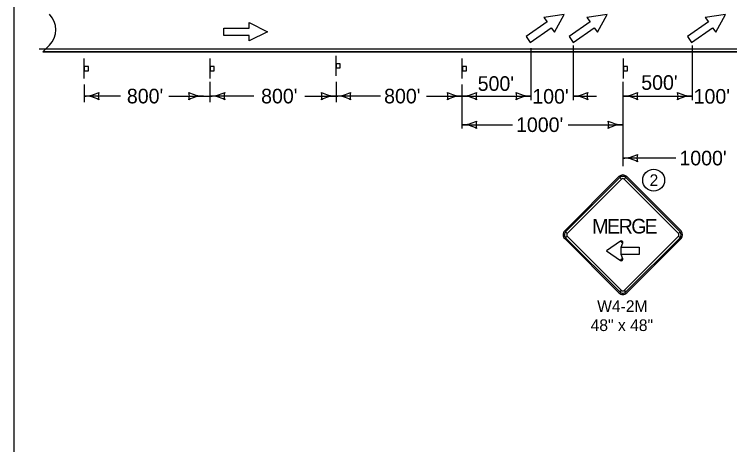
# Model space of a CAD drawing. Extents: x 10133 to 2270741, y 5363 to 1733450.
# Drawn here: x 28133 to 29111, y 8710 to 9298 of the extents above; entities that cross this region are included whole.
import ezdxf

# ---------------------------------------------------------------- set-up
doc = ezdxf.new("R2010")
doc.units = 0
for name, color, linetype in [('dsnNonPlotable', 7, 'Continuous'), ('dsnShtPlotShapeBatchPrint', 7, 'Continuous'), ('dsnStdBorder', 7, 'Continuous'), ('Level 12', 7, 'Continuous'), ('Level 2', 7, 'Continuous'), ('SheetBorder', 7, 'Continuous'), ('SheetText', 7, 'Continuous')]:
    doc.layers.add(name, color=color, linetype=linetype)

msp = doc.modelspace()

# ---------------------------------------------------------------- linework, layer by layer
at = {"layer": 'dsnNonPlotable'}
for p, q in [((28884.31, 9298.24), (28856.66, 9294.14)), ((28856.66, 9294.14), (28860.96, 9288)), ((28871, 9273.67), (28884.31, 9298.24)), ((28943.08, 9298.24), (28915.43, 9294.14)), ((28915.43, 9294.14), (28919.73, 9288)), ((28929.77, 9273.67), (28943.08, 9298.24)), ((29104.88, 9298.24), (29077.24, 9294.14)), ((29077.24, 9294.14), (29081.54, 9288)), ((29091.58, 9273.67), (29104.88, 9298.24)), ((28860.96, 9288), (28832.3, 9267.93)), ((28919.73, 9288), (28891.07, 9267.93)), ((29081.54, 9288), (29052.87, 9267.93)), ((28838.03, 9259.74), (28866.7, 9279.81)), ((28866.7, 9279.81), (28871, 9273.67)), ((28896.8, 9259.74), (28925.47, 9279.81)), ((28925.47, 9279.81), (28929.77, 9273.67)), ((29058.61, 9259.74), (29087.28, 9279.81)), ((29087.28, 9279.81), (29091.58, 9273.67)), ((28832.3, 9267.93), (28838.03, 9259.74)), ((28891.07, 9267.93), (28896.8, 9259.74)), ((29052.87, 9267.93), (29058.61, 9259.74)), ((28180.53, 9255.86), (28171.75, 9247.08)), ((28166.53, 9251.04), (29674.01, 9251.04))]:
    msp.add_line(p, q, dxfattribs=at)
msp.add_arc((28159.32, 9277.08), 30, 315, 45, dxfattribs=at)
at = {"layer": 'dsnShtPlotShapeBatchPrint'}
msp.add_circle((29006.75, 9071.41), 15, dxfattribs=at)
at = {"layer": 'dsnStdBorder'}
for p, q in [((28959.31, 9076.33), (28885.06, 9002.08)), ((28960.64, 9075), (28962.85, 9072.8)), ((28966.38, 9072.8), (28968.59, 9075)), ((29044.16, 9002.08), (28969.92, 9076.33)), ((28888.6, 8998.55), (28886.39, 9000.76)), ((29042.84, 9000.76), (29040.63, 8998.55)), ((28885.06, 8991.48), (28959.31, 8917.23)), ((28886.39, 8992.8), (28888.6, 8995.01)), ((28969.92, 8917.23), (29044.16, 8991.48)), ((29040.63, 8995.01), (29042.84, 8992.8)), ((28961.5, 8988.19), (28962.58, 8986.47)), ((28962.58, 8986.47), (28964.51, 8985.82)), ((28962.58, 8963.34), (28961.5, 8961.63)), ((28964.51, 8963.99), (28962.58, 8963.34)), ((28962.85, 8920.77), (28960.64, 8918.56)), ((28968.59, 8918.56), (28966.38, 8920.77))]:
    msp.add_line(p, q, dxfattribs=at)
for points in [[(28960.64, 9075), (28886.39, 9000.76), (28888.6, 8998.55), (28962.85, 9072.8), (28960.64, 9075)], [(29042.84, 9000.76), (28968.59, 9075), (28966.38, 9072.8), (29040.63, 8998.55), (29042.84, 9000.76)], [(28886.39, 8992.8), (28960.64, 8918.56), (28962.85, 8920.77), (28888.6, 8995.01), (28886.39, 8992.8)], [(28968.59, 8918.56), (29042.84, 8992.8), (29040.63, 8995.01), (28966.38, 8920.77), (28968.59, 8918.56)], [(28942.27, 8974.91), (28961.5, 8961.63), (28962.58, 8963.34), (28964.51, 8963.99), (28962.52, 8969.91), (28962.52, 8979.91), (28964.51, 8985.82), (28962.58, 8986.47), (28961.5, 8988.19), (28942.27, 8974.91)], [(28986.96, 8979.91), (28986.96, 8969.91), (28962.52, 8969.91), (28962.52, 8979.91), (28986.96, 8979.91)]]:
    msp.add_lwpolyline(points, close=True, dxfattribs=at)
for centre, radius, start, end in [((28964.61, 9071.03), 7.5, 44.99999, 134.99974), ((28964.61, 9071.03), 5.62, 44.99999, 134.99974), ((28964.61, 9071.03), 2.5, 44.99999, 134.99974), ((28890.37, 8996.78), 7.5, 134.99974, 224.99995), ((28890.37, 8996.78), 5.62, 134.99974, 224.99995), ((29038.86, 8996.78), 5.62, 315.00016, 44.9998), ((29038.86, 8996.78), 7.5, 315.00016, 44.9998), ((28890.37, 8996.78), 2.5, 134.99974, 224.99995), ((29038.86, 8996.78), 2.5, 315.00016, 44.9998), ((28962.58, 8986.47), 2.03, 341.41867, 122.31243), ((28962.58, 8963.34), 2.03, 237.68753, 18.58186), ((28964.61, 8922.54), 7.5, 224.99995, 315.00016), ((28964.61, 8922.54), 5.62, 224.99995, 315.00016), ((28964.61, 8922.54), 2.5, 224.99995, 315.00016)]:
    msp.add_arc(centre, radius, start, end, dxfattribs=at)
at = {"layer": 'Level 12'}
for p, q in [((28896.54, 9255.48), (28896.54, 9180.88)), ((29059.3, 9255.48), (29059.3, 9180.88)), ((28838.72, 9252.13), (28838.72, 9180.88)), ((28399.86, 9206.09), (28399.86, 9178.34)), ((28572.44, 9206.09), (28572.44, 9178.34)), ((28964.61, 9206.09), (28964.61, 9090.8)), ((28228.05, 9202.35), (28228.05, 9178.34)), ((28744.62, 9202.35), (28744.62, 9142.32)), ((28277.9, 9186.46), (28230.85, 9186.46)), ((28343.6, 9186.46), (28399.86, 9186.46)), ((28460.08, 9186.46), (28399.86, 9186.46)), ((28529.73, 9186.46), (28572.44, 9186.46)), ((28633.22, 9186.46), (28572.44, 9186.46)), ((28696.14, 9186.46), (28744.42, 9186.46)), ((28745.22, 9186.46), (28812.94, 9186.46)), ((28812.94, 9186.46), (28838.72, 9186.46)), ((28896.54, 9186.46), (28928.54, 9186.46)), ((28965.43, 9186.46), (29034.79, 9186.46)), ((29034.79, 9186.46), (29059.3, 9186.46)), ((28744.42, 9147.32), (28813.6, 9147.32)), ((28889.64, 9147.32), (28964.61, 9147.32)), ((29037.15, 9101.68), (28964.61, 9101.68))]:
    msp.add_line(p, q, dxfattribs=at)
for centre, radius, start, end in [((28228.16, 9228.96), 42.5, 270, 298.07249), ((28228.16, 9143.96), 42.5, 61.92751, 90), ((28263.8, 9186.46), 16.42, 162.26665, 197.73335), ((28355.52, 9186.46), 16.42, 342.26665, 17.73335), ((28391.15, 9228.96), 42.5, 241.92751, 270), ((28391.15, 9143.96), 42.5, 90, 118.07249), ((28400.25, 9228.96), 42.5, 270, 298.07249), ((28400.25, 9143.96), 42.5, 61.92751, 90), ((28435.88, 9186.46), 16.42, 162.26665, 197.73335), ((28536.79, 9186.46), 16.42, 342.26665, 17.73335), ((28572.42, 9228.96), 42.5, 241.92751, 270), ((28572.42, 9143.96), 42.5, 90, 118.07249), ((28572.42, 9228.96), 42.5, 270, 298.07249), ((28572.42, 9143.96), 42.5, 61.92751, 90), ((28608.06, 9186.46), 16.42, 162.26665, 197.73335), ((28708.98, 9186.46), 16.42, 342.26665, 17.73335), ((28744.62, 9228.96), 42.5, 241.92751, 270), ((28744.62, 9143.96), 42.5, 90, 118.07249), ((28744.62, 9228.96), 42.5, 270, 298.07249), ((28744.62, 9143.96), 42.5, 61.92751, 90), ((28780.26, 9186.46), 16.42, 162.26665, 197.73335), ((28803.08, 9186.46), 16.42, 342.26665, 17.73335), ((28838.72, 9228.96), 42.5, 241.92751, 270), ((28838.72, 9143.96), 42.5, 90, 118.07249), ((28896.54, 9228.96), 42.5, 270, 298.07249), ((28896.54, 9143.96), 42.5, 61.92751, 90), ((28932.18, 9186.46), 16.42, 162.26665, 197.73335), ((28964.83, 9228.96), 42.5, 270, 298.07249), ((28964.83, 9143.96), 42.5, 61.92751, 90), ((29000.47, 9186.46), 16.42, 162.26665, 197.73335), ((29023.66, 9186.46), 16.42, 342.26665, 17.73335), ((29059.3, 9228.96), 42.5, 241.92751, 270), ((29059.3, 9143.96), 42.5, 90, 118.07249), ((28744.62, 9189.82), 42.5, 270, 298.07249), ((28744.62, 9104.82), 42.5, 61.92751, 90), ((28780.26, 9147.32), 16.42, 162.26665, 197.73335), ((28928.98, 9147.32), 16.42, 342.26665, 17.73335), ((28964.61, 9189.82), 42.5, 241.92751, 270), ((28964.61, 9104.82), 42.5, 90, 118.07249), ((28964.61, 9144.18), 42.5, 270, 298.07249), ((28964.61, 9059.18), 42.5, 61.92751, 90), ((29000.25, 9101.68), 16.42, 162.26665, 197.73335)]:
    msp.add_arc(centre, radius, start, end, dxfattribs=at)
at = {"layer": 'Level 2'}
for p, q in [((28171.75, 9247.06), (28180.53, 9255.87)), ((28171.75, 9247.06), (30467.95, 9247.06)), ((29180.22, 9247.06), (28171.75, 9247.06))]:
    msp.add_line(p, q, dxfattribs=at)
msp.add_arc((28159.32, 9277.08), 30, 315, 45, dxfattribs=at)
at = {"layer": 'SheetBorder'}
msp.add_lwpolyline([(28132.52, 9944.02), (31267.53, 9944.02), (31267.53, 7924.02), (28132.52, 7924.02)], close=True, dxfattribs=at)
at = {"layer": 'SheetText'}
for p, q in [((28228.05, 9210.35), (28228.05, 9237.85)), ((28400.25, 9210.35), (28400.25, 9237.85)), ((28572.44, 9214.09), (28572.44, 9241.59)), ((28745.07, 9210.35), (28745.07, 9237.85)), ((28965.28, 9210.35), (28965.28, 9237.85))]:
    msp.add_line(p, q, dxfattribs=at)
msp.add_lwpolyline([(28418.82, 9269.4), (28418.82, 9279.4), (28453.82, 9279.4), (28453.82, 9286.9), (28478.82, 9274.4), (28453.82, 9261.9), (28453.82, 9269.4), (28418.82, 9269.4)], dxfattribs=at)
for points in [[(28228.15, 9226.8), (28228.15, 9221.18), (28233.77, 9221.18), (28233.77, 9226.8)], [(28400.34, 9226.8), (28400.34, 9221.18), (28405.97, 9221.18), (28405.97, 9226.8)], [(28572.54, 9230.54), (28572.54, 9224.91), (28578.16, 9224.91), (28578.16, 9230.54)], [(28745.16, 9226.8), (28745.16, 9221.18), (28750.79, 9221.18), (28750.79, 9226.8)], [(28965.37, 9226.8), (28965.37, 9221.18), (28971, 9221.18), (28971, 9226.8)]]:
    msp.add_lwpolyline(points, close=True, dxfattribs=at)

# ---------------------------------------------------------------- texts
at = {"layer": 'dsnShtPlotShapeBatchPrint'}
msp.add_text('2', height=16, dxfattribs=at).set_placement((29001.13, 9063.41))
at = {"layer": 'dsnStdBorder'}
for s, height, p in [('M', 20, (28922.73, 8998.5)), ('E', 20, (28942.94, 8998.5)), ('R', 20, (28958.91, 8998.5)), ('G', 20, (28976.14, 8998.5)), ('E', 20, (28994.31, 8998.5)), ('W4-2M', 16, (28929.45, 8891.11)), ('48" x 48"', 16, (28920.55, 8865.11))]:
    msp.add_text(s, height=height, dxfattribs=at).set_placement(p)
at = {"layer": 'Level 12'}
for s, p in [("500'", (28989.74, 9194.98)), ("500'", (28766.09, 9193.6)), ("800'", (28286.44, 9176.46)), ("800'", (28470.01, 9176.46)), ("800'", (28638.18, 9176.46)), ("100'", (28840.79, 9176.1)), ("100'", (29061.37, 9176.1)), ("1000'", (28818.53, 9137.32)), ("1000'", (29041.94, 9091.68))]:
    msp.add_text(s, height=20, dxfattribs=at).set_placement(p)

doc.saveas('drawing.dxf')
